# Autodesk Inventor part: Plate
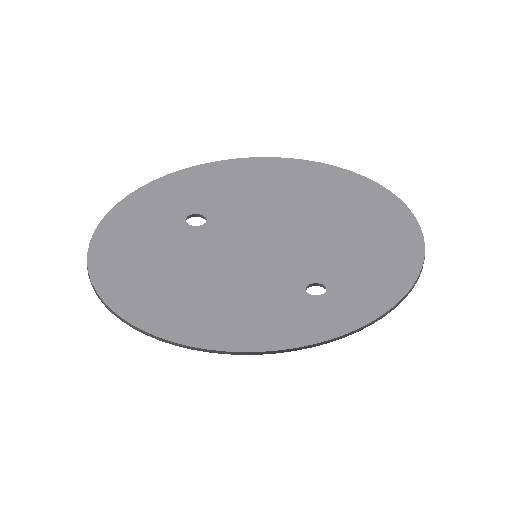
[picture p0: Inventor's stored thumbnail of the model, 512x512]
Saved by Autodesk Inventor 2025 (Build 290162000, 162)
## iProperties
Created: 2009-04
Part Number: Plate
Document SubType Name: Modeling
Designer: Sham
Density: 1 g/cm^3
Material: Generic
Appearance: Default
Author: Sham
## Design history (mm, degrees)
sketch "Sketch1"
  geometry: C1 r 6.25 at (-50, 0); C2 r 6.25 at (50, 0); 4 further points
  constraints: 2 centre point, 1 coincident, 5 other
  dimensions: "d1" = 12.5 diameter of C1; "d2" = 12.5 diameter of C2; "d3" = 100 distance of C2.centre C1.centre; "d4" = 102.5 distance of point (0, 0) point (0, 102.5); "d5" = 96.9 distance of point (0, 0) point (-96.9, 0); "d6" = 50 distance of point (0, 0) C1.centre
extrude "Extrusion1" new body sketch "Sketch1" distance "d7" = 2; taper "d8" = 0 deg
body "Solid1"
